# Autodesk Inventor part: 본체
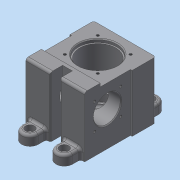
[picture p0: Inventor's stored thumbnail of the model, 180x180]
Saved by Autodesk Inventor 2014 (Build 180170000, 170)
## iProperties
Created: 2024-11
Part Number: 본체
Material: 일반
Document SubType Name: Modeling
Designer: dg
Density: 1 g/cm^3
Appearance: 기본값
Author: dg
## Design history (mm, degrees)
sketch "스케치1"
  geometry: L1 (-38, 29)-(38, 29); L2 (-36, -56)-(-6, -56); L3 (-6, -56)-(-6, -41); L4 (-6, -41)-(6, -41); L5 (6, -41)-(6, -56); L6 (6, -56)-(36, -56); L7 (38, 29)-(38, 0); L8 (38, 0)-(36, 0); L9 (36, 0)-(36, -56); L10 (-38, 29)-(-38, 0); L11 (-38, 0)-(-36, 0); L12 (-36, 0)-(-36, -56); 2 further points
  constraints: 24 end point, 4 vertical, 3 perpendicular, 2 collinear, 2 horizontal, 2 parallel, 1 horizontal alignment, 1 midpoint, 1 vertical alignment
  dimensions: "d0" = 76 distance of L1.start L1.end; "d3" = 2 distance of L7.end L8.end; "d4" = 56 distance of L8.end L6.end; "d5" = 12 distance of L3.end L4.end; "d7" = 85 distance from line of L2.start L1; "d8" = 56 distance of L11.end L2.start; "d9" = 2 distance of L10.end L11.end; "d10" = 29 distance of point (0, 0) point (0, 29); "d11" = 15 distance between parallel lines of L6 L4
extrude "돌출1" new body sketch "스케치1" distance "d12" = 70; taper "d13" = 0 deg
sketch "스케치2"
  geometry: L1 (-38, 29)-(38, 29) reference; L2 (-36, -56)-(-36, 0) reference; L3 (-6, -56)-(-36, -56) reference; L4 (-6, -41)-(-6, -56) reference; L5 (6, -41)-(-6, -41) reference; L6 (6, -56)-(6, -41) reference; L7 (36, -56)-(6, -56) reference; L8 (36, 0)-(36, -56) reference; L9 (38, 29)-(38, 0) reference; L10 (-36, -37)-(36, -37); 1 further point
  constraints: 2 end point, 2 point on line, 1 perpendicular
  dimensions: "d14" = 66 distance between parallel lines of L10 L1
extrude "돌출2" join sketch "스케치2" distance "d15" = 4; taper "d16" = 0 deg
sketch "스케치3"
  geometry: L1 (38, 29)-(-38, 29) reference; L2 (-36, -56)-(-6, -56) reference; L3 (6, -56)-(36, -56) reference; L4 (-31, 39)-(-31, 29); L5 (31, 39)-(31, 29); L6 (11, 39)-(11, 29); L7 (-11, 39)-(-11, 29); L8 (-11, -66)-(-11, -56); L9 (-31, -66)-(-31, -56); L10 (11, -66)-(11, -56); L11 (31, -66)-(31, -56); A1 r 10 centre (-21, 39) between (-11, 39) and (-31, 39); A2 r 10 centre (21, 39) between (31, 39) and (11, 39); A3 r 10 centre (-21, -66) between (-31, -66) and (-11, -66); A4 r 10 centre (21, -66) between (11, -66) and (31, -66); 1 further point
  constraints: 16 end point, 10 point on circle, 10 point on line, 8 tangent, 7 perpendicular, 5 horizontal alignment, 4 centre point, 3 equal radius, 2 equal length, 2 vertical alignment, 1 collinear
  dimensions: "d17" = 20 distance between parallel lines of L5 L6; "d18" = 42 distance of A1.centre A2.centre; "d19" = 10 distance of L4.start L4.end; "d20" = 17 horizontal distance of L1.start A2.centre
extrude "돌출3" join sketch "스케치3" distance "d21" = 12; taper "d22" = 0 deg
sketch "스케치4"
  geometry: L1 (-38, 29)-(38, 29) reference; C1 r 23.5 at (0, -4); 1 further point
  constraints: 1 centre point, 1 vertical alignment
  dimensions: "d24" = 33 distance from line of L1 C1.centre; "d25" = 47 diameter of C1
extrude "돌출4" cut sketch "스케치4" distance "d26" = 4; taper "d27" = 0 deg
sketch "스케치5"
  geometry: C1 r 23.5 at (0, 0) reference; C2 r 22 at (0, 0); 1 further point
  constraints: 1 centre point, 1 coincident
  dimensions: "d28" = 44 diameter of C2
extrude "돌출5" cut sketch "스케치5" distance "d29" = 48; taper "d30" = 0 deg
sketch "스케치6"
  geometry: C1 r 22 at (0, 0) reference; C2 r 17.5 at (0, 0); 1 further point
  constraints: 1 centre point, 1 coincident
  dimensions: "d31" = 35 diameter of C2
extrude "돌출6" cut sketch "스케치6" distance "d32" = 11; taper "d33" = 0 deg
sketch "스케치7"
  geometry: C1 r 17.5 at (0, 0) reference; C2 r 15 at (0, 0); 1 further point
  constraints: 1 centre point, 1 coincident
  dimensions: "d34" = 30 diameter of C2
extrude "돌출7" cut sketch "스케치7" distance "d35" = 3; taper "d36" = 0 deg
fillet "모깎기1" dims "d37" = 3
fillet "모깎기2" dims "d38" = 0.6
chamfer "모따기1" distance "d39" = 1; stored, may be unused: second distance "d40" = 2, angle "d41" = 45 deg
chamfer "모따기2" distance "d42" = 1; stored, may be unused: second distance "d43" = 2, angle "d44" = 45 deg
sketch "스케치8"
  geometry: L1 (0, 0)-(0, 56) reference; L2 (70, 85)-(0, 85) reference; C1 r 16.5 at (42, 28)
  constraints: 1 centre point
  dimensions: "d45" = 42 distance from line of L1 C1.centre; "d46" = 33 diameter of C1; "d47" = 57 distance from line of C1.centre L2
extrude "돌출8" cut sketch "스케치8" stored distance "d48" = 3; taper "d49" = 0 deg
sketch "스케치9"
  geometry: L1 (31, -56)-(31, -66) reference; L2 (11, -66)-(11, -56) reference; L3 (31, -56)-(11, -56) reference; L4 (36, -56)-(31, -56) reference; L5 (36, 0)-(36, -56) reference; L6 (38, 0)-(36, 0) reference; L7 (38, 29)-(38, 0) reference; L8 (31, 29)-(38, 29) reference; L9 (31, 39)-(31, 29) reference; L10 (11, 29)-(11, 39) reference; L11 (-11, 29)-(11, 29) reference; L12 (-11, 39)-(-11, 29) reference; L13 (-31, 29)-(-31, 39) reference; L14 (-38, 29)-(-31, 29) reference; L15 (-38, 0)-(-38, 29) reference; L16 (-36, 0)-(-38, 0) reference; L17 (-36, -56)-(-36, 0) reference; L18 (-31, -56)-(-36, -56) reference; L19 (-31, -66)-(-31, -56) reference; L20 (-11, -56)-(-11, -66) reference; L21 (-6, -56)-(-11, -56) reference; L22 (-6, -41)-(-6, -56) reference; L23 (6, -41)-(-6, -41) reference; L24 (6, -56)-(6, -41) reference; L25 (11, -56)-(6, -56) reference; L26 (11, 29)-(31, 29) reference; L27 (-31, 29)-(-11, 29) reference; L28 (-11, -56)-(-31, -56) reference; C1 r 17.5 at (0, -4) reference; A1 r 10 centre (21, -66) between (11, -66) and (31, -66) reference; A2 r 10 centre (21, 39) between (31, 39) and (11, 39) reference; A3 r 10 centre (-21, 39) between (-11, 39) and (-31, 39) reference; A4 r 10 centre (-21, -66) between (-31, -66) and (-11, -66) reference; 5 further points
  constraints: 4 coincident
hole "구멍1" sketch "스케치9" at (-21, 39), (21, 39), (-21, -66), (21, -66) diameter "d50" = 6.6; stored, may be unused: countersink angle "d54" = 90 deg, drill point angle "d56" = 118 deg; dims "d51" = 6, "d52" = 11, "d53" = 6.6, "d55" = 8
sketch "스케치10"
  geometry: L1 (74, -4)-(2, -4) reference; 4 further points
  constraints: 1 midpoint, 1 vertical alignment, 1 other
  dimensions: "d57" = 20 vertical distance of point (76, 0) point (38, 20)
feature "엠보싱1" sketch "스케치10" dims "d58" = 0.5, "d59" = 0
fillet "모깎기3" dims "d60" = 3
fillet "모깎기4" dims "d61" = 3
fillet "모깎기5" dims "d62" = 3
chamfer "모따기3" distance "d64" = 1; stored, may be unused: second distance "d65" = 2, angle "d66" = 45 deg
chamfer "모따기4" distance "d67" = 1; stored, may be unused: second distance "d68" = 2, angle "d69" = 45 deg
sketch "스케치11"
  geometry: L1 (-35, 29)-(35, 29) reference; L2 (0, -4)-(20.153, 16.153); L3 (0, -4)-(28.5, -4); C1 r 24.5 at (0, -4) reference; A1 r 28.5 centre (0, -4) between (20.153, 16.153) and (28.5, -4); 2 further points
  constraints: 4 end point, 2 coincident, 2 point on circle, 1 centre point, 1 parallel
  dimensions: "d71" = 57 diameter of A1; "d72" = 45 deg angle of L3 L2
hole "구멍2" sketch "스케치11" at (20.153, 16.153) diameter "d73" = 3.242; stored, may be unused: countersink angle "d77" = 90 deg, drill point angle "d79" = 118 deg; dims "d74" = 8, "d75" = 11, "d76" = 6.6, "d78" = 10
sketch "스케치12"
  geometry: C1 r 17.5 at (42, 28) reference; 4 further points
  constraints: 2 horizontal alignment, 2 vertical alignment
  dimensions: "d83" = 32 distance of point (26, 12) point (26, 44); "d84" = 32 distance of point (58, 12) point (26, 12); "d85" = 16 horizontal distance of C1.centre point (58, 12); "d86" = 16 horizontal distance of C1.centre point (26, 44)
hole "구멍3" sketch "스케치12" at (26, 44), (58, 44), (58, 12), (26, 12) diameter "d87" = 3.242; stored, may be unused: countersink angle "d91" = 90 deg, drill point angle "d93" = 118 deg; dims "d88" = 8, "d89" = 11, "d90" = 6.6, "d92" = 10
sketch "스케치13"
  geometry: L1 (0, 0)-(12, 0) reference; L2 (-29, -42.161)-(0, -42.161) reference; L3 (0, -42.161)-(12, -42.161) reference; L4 (12, -42.161)-(41, -42.161) reference; L5 (42, -43.715)-(42, -74) reference; L6 (42, -74)-(12, -74) reference; L7 (12, -74)-(0, -74) reference; L8 (0, -74)-(-30, -74) reference; L9 (-30, -74)-(-30, -43.715) reference; L10 (0, -42.161)-(0, -74) reference; L11 (12, -74)-(12, -42.161) reference; L12 (41, -21.839)-(12, -21.839) reference; L13 (12, -21.839)-(0, -21.839) reference; L14 (0, -21.839)-(-29, -21.839) reference; L15 (-30, -20.285)-(-30, 0) reference; L16 (-30, 0)-(0, 0) reference; L17 (0, 0)-(0, -21.839) reference; L18 (42, 0)-(42, -20.285) reference; L19 (12, 0)-(42, 0) reference; L20 (12, -21.839)-(12, 0) reference; L21 (0, 0)-(12, 0) reference; 3 further points
  constraints: 2 vertical alignment, 4 other
  dimensions: "d94" = 12 distance from line of L1 point (6, -12); "d95" = 40 distance of point (6, -52) point (6, -12)
hole "구멍4" sketch "스케치13" at (6, -12), (6, -52) diameter "d96" = 3.242; stored, may be unused: countersink angle "d100" = 90 deg, drill point angle "d102" = 118 deg; dims "d97" = 8, "d98" = 11, "d99" = 6.6, "d101" = 10
chamfer "모따기5" distance "d103" = 1; stored, may be unused: second distance "d104" = 2, angle "d105" = 45 deg
fillet "모깎기7" dims "d106" = 3
node "솔리드1"
pattern_circular "원형 패턴1" dims angle "d81" = 360 deg
mirror "대칭1"
node "작업 평면1"
node "절단 모서리 투영1"
node "절단 모서리 투영2"
